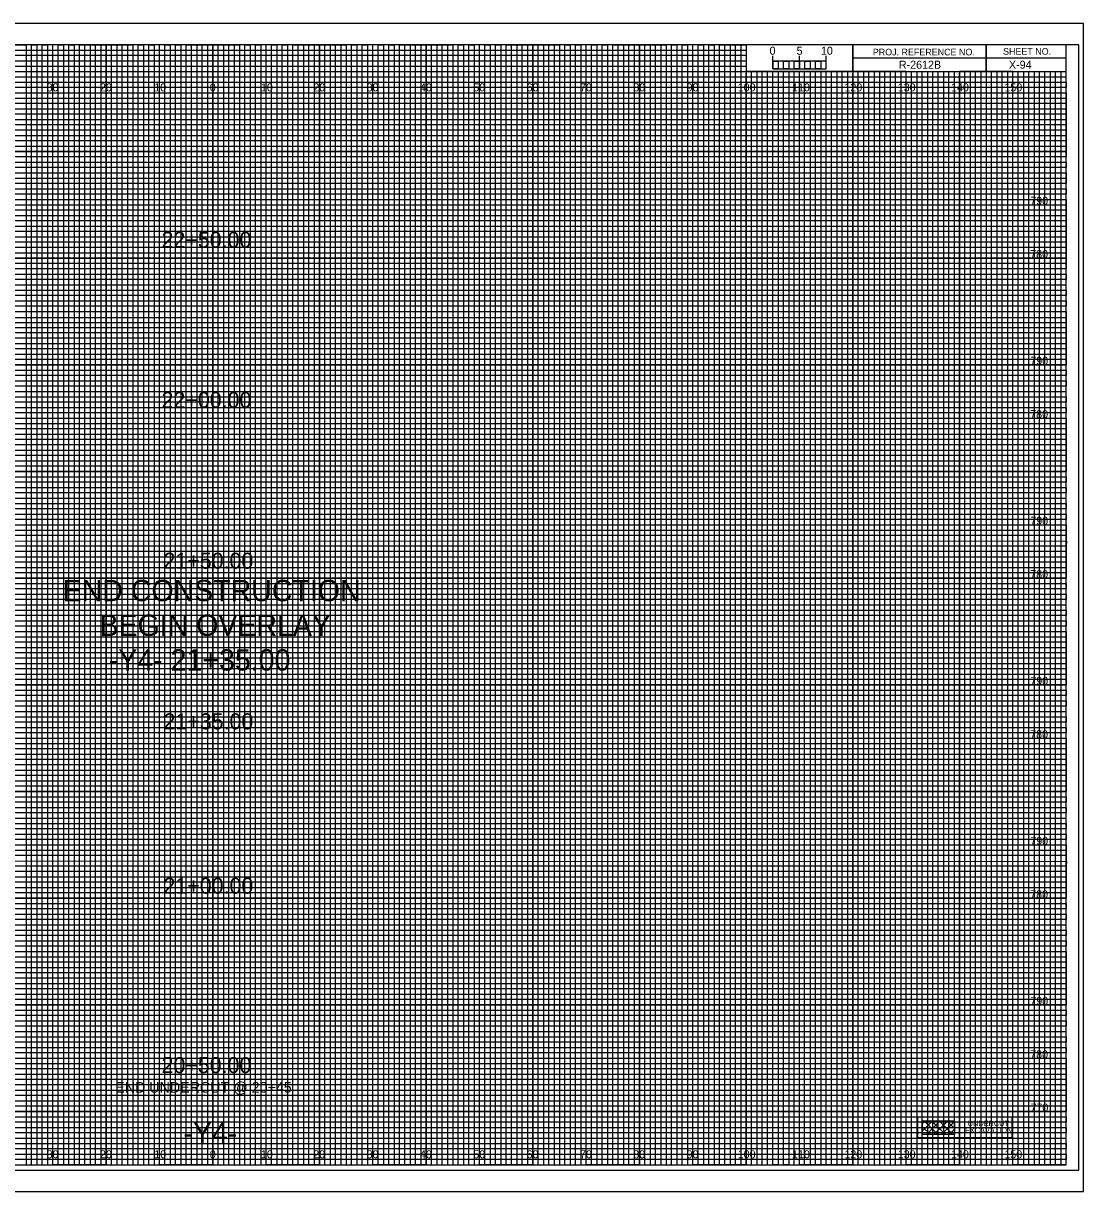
# Model space of a CAD drawing. Extents: x -13 to 323, y 875 to 1094.
# Drawn here: x 124.5 to 323.3, y 875 to 1094 of the extents above; entities that cross this region are included whole.
import ezdxf

# ---------------------------------------------------------------- set-up
doc = ezdxf.new("R2010")
doc.units = 0
for name, color, linetype in [('Prop Grid Mask', 7, 'Continuous'), ('Prop XS Alignment Label', 7, 'Continuous'), ('Prop XS Bar Scale Labels', 7, 'Continuous'), ('Prop XS Elevation Labels', 7, 'Continuous'), ('Prop XS Offset Labels', 7, 'Continuous'), ('Prop XS Project Number', 7, 'Continuous'), ('Prop XS Sheet Number', 7, 'Continuous'), ('Prop XS Station Labels', 7, 'Continuous'), ('Prop XS Undercut Exc Hatch', 7, 'Continuous'), ('Prop XSC Text', 7, 'Continuous'), ('Sheet Cross Section CELL', 7, 'Continuous'), ('Sheet Cross Section Grid Major CELL', 7, 'Continuous'), ('Sheet Cross Section Grid Middle CELL', 7, 'Continuous'), ('Sheet Cross Section Grid Minor 1 CELL', 7, 'Continuous'), ('Sheet Cross Section Grid Minor 2 CELL', 7, 'Continuous'), ('Sheet Cross Section Scale CELL', 7, 'Continuous'), ('Sheet Cutting Line CELL', 7, 'Continuous'), ('Sheet DOT Grid CELL', 7, 'Continuous'), ('Sheet Plot Border Inside CELL', 7, 'Continuous'), ('Sheet Plot Border Outside CELL', 7, 'Continuous')]:
    doc.layers.add(name, color=color, linetype=linetype)

msp = doc.modelspace()

# ---------------------------------------------------------------- linework, layer by layer
at = {"layer": 'Prop Grid Mask'}
for points in [[(292.21, 889.05), (309.86, 889.05), (309.86, 885.11), (292.21, 885.11)], [(293.02, 885.76), (299.12, 885.76), (299.12, 888.23), (293.02, 888.23)]]:
    msp.add_lwpolyline(points, close=True, dxfattribs=at)
at = {"layer": 'Prop XS Undercut Exc Hatch'}
for p, q in [((293.02, 887.74), (293.51, 888.23)), ((293.02, 886.33), (294.93, 888.23)), ((293.02, 887.24), (294.5, 885.76)), ((293.44, 888.23), (295.91, 885.76)), ((293.87, 885.76), (296.34, 888.23)), ((294.86, 888.23), (297.32, 885.76)), ((295.29, 885.76), (297.75, 888.23)), ((296.27, 888.23), (298.74, 885.76)), ((296.7, 885.76), (299.12, 888.18)), ((297.69, 888.23), (299.12, 886.79)), ((299.1, 888.23), (299.12, 888.21)), ((293.02, 885.82), (293.08, 885.76)), ((298.12, 885.76), (299.12, 886.77))]:
    msp.add_line(p, q, dxfattribs=at)
at = {"layer": 'Sheet Cross Section CELL'}
for p, q in [((305, 1090), (305, 1085)), ((305, 1085), (305, 1090)), ((280, 1087.5), (280, 1085)), ((320, 1087.49), (280, 1087.49)), ((280, 1085), (320, 1085))]:
    msp.add_line(p, q, dxfattribs=at)
for points in [[(320, 1090), (0, 1090), (0, 880), (320, 880)], [(280, 1090), (260, 1090), (260, 1085.03), (280, 1085.03)], [(320, 1090), (280, 1090), (280, 1085), (320, 1085)]]:
    msp.add_lwpolyline(points, close=True, dxfattribs=at)
at = {"layer": 'Sheet Cross Section Grid Major CELL'}
for p, q in [((130, 1090), (120, 1090)), ((130, 880), (130, 1090)), ((150, 1090), (140, 1090)), ((140, 1090), (140, 880)), ((150, 880), (150, 1090)), ((170, 1090), (160, 1090)), ((160, 1090), (160, 880)), ((170, 880), (170, 1090)), ((190, 1090), (180, 1090)), ((180, 1090), (180, 880)), ((190, 880), (190, 1090)), ((210, 1090), (200, 1090)), ((200, 1090), (200, 880)), ((210, 880), (210, 1090)), ((230, 1090), (220, 1090)), ((220, 1090), (220, 880)), ((230, 880), (230, 1090)), ((250, 1090), (240, 1090)), ((240, 1090), (240, 880)), ((250, 880), (250, 1090)), ((260, 1090), (260, 880)), ((270, 880), (270, 1085)), ((290, 1085), (280, 1085)), ((280, 1085), (280, 880)), ((290, 880), (290, 1085)), ((310, 1085), (300, 1085)), ((300, 1085), (300, 880)), ((310, 880), (310, 1085)), ((140, 880), (130, 880)), ((160, 880), (150, 880)), ((180, 880), (170, 880)), ((200, 880), (190, 880)), ((220, 880), (210, 880)), ((240, 880), (230, 880)), ((260, 880), (250, 880)), ((280, 880), (270, 880)), ((300, 880), (290, 880)), ((320, 880), (310, 880)), ((320, 880), (320, 880))]:
    msp.add_line(p, q, dxfattribs=at)
for points in [[(0, 1080), (320, 1080), (320, 1070), (0, 1070)], [(0, 1060), (320, 1060), (320, 1050), (0, 1050)], [(0, 1040), (320, 1040), (320, 1030), (0, 1030)], [(0, 1020), (320, 1020), (320, 1010), (0, 1010)], [(0, 1000), (320, 1000), (320, 990), (0, 990)], [(0, 980), (320, 980), (320, 970), (0, 970)], [(0, 960), (320, 960), (320, 950), (0, 950)], [(0, 940), (320, 940), (320, 930), (0, 930)], [(0, 920), (320, 920), (320, 910), (0, 910)], [(0, 900), (320, 900), (320, 890), (0, 890)]]:
    msp.add_lwpolyline(points, dxfattribs=at)
at = {"layer": 'Sheet Cross Section Grid Middle CELL'}
for points in [[(115, 1090), (125, 1090), (125, 880), (135, 880), (135, 1090), (145, 1090), (145, 880), (155, 880), (155, 1090), (165, 1090), (165, 880), (175, 880), (175, 1090), (185, 1090), (185, 880), (195, 880), (195, 1090), (205, 1090), (205, 880), (215, 880), (215, 1090), (225, 1090), (225, 880), (235, 880), (235, 1090), (245, 1090), (245, 880), (255, 880), (255, 1090), (259.93, 1090), (260, 1090), (260, 1085), (264.99, 1085), (264.99, 880), (275, 880), (275, 1085), (285, 1085), (285, 880), (295, 880), (295, 1085), (305, 1085), (305, 880), (315, 880), (315, 1085)], [(0, 1085), (275, 1085)], [(0, 1065), (320, 1065), (320, 1075), (0, 1075)], [(0, 1045), (320, 1045), (320, 1055), (0, 1055)], [(0, 1025), (320, 1025), (320, 1035), (0, 1035)], [(0, 1005), (320, 1005), (320, 1015), (0, 1015)], [(0, 985), (320, 985), (320, 995), (0, 995)], [(0, 965), (320, 965), (320, 975), (0, 975)], [(0, 945), (320, 945), (320, 955), (0, 955)], [(0, 925), (320, 925), (320, 935), (0, 935)], [(0, 905), (320, 905), (320, 915), (0, 915)], [(0, 885), (320, 885), (320, 895), (0, 895)]]:
    msp.add_lwpolyline(points, dxfattribs=at)
at = {"layer": 'Sheet Cross Section Grid Minor 1 CELL'}
for p, q in [((0, 1089), (260, 1089)), ((260, 1089), (260, 1087.98)), ((260, 1087.98), (0, 1087.98)), ((0, 1087), (260, 1087)), ((260, 1087), (260, 1085.89)), ((260, 1085.89), (0, 1085.89)), ((0, 1084), (320, 1084))]:
    msp.add_line(p, q, dxfattribs=at)
for points in [[(0, 1083), (270, 1083), (320, 1083), (320, 1082), (0, 1082)], [(0, 1081), (320, 1081), (320, 1079), (0, 1079)], [(0, 1078), (320, 1078), (320, 1077), (0, 1076.98)], [(0, 1076), (320, 1076), (320, 1074), (0, 1074)], [(0, 1073), (320, 1073), (320, 1072), (0, 1072)], [(0, 1071), (320, 1071), (320, 1069), (0, 1069)], [(0, 1068), (320, 1068), (320, 1067), (0, 1067)], [(0, 1066), (320, 1066), (320, 1064), (0, 1064)], [(0, 1063), (320, 1063), (320, 1062), (0, 1062)], [(0, 1061), (320, 1061), (320, 1059), (0, 1059)], [(0, 1058), (320, 1058), (320, 1057), (0, 1057)], [(0, 1056), (320, 1056), (320, 1053.95), (320, 1053), (320, 1052), (0, 1052)], [(0, 1054), (320, 1054), (320, 1053), (0, 1053)], [(0, 1051), (320, 1051), (320, 1049), (0, 1049.03)], [(0, 1049.03), (320, 1049), (320, 1048), (0, 1048)], [(0, 1047), (320, 1047), (320, 1046), (0, 1046)], [(0, 1044), (320, 1044), (320, 1043), (0, 1043)], [(0, 1042), (320, 1042), (320, 1041), (0, 1041)], [(-0.07, 1038.89), (320, 1038.89), (320, 1037.88), (-0.07, 1037.88)], [(0, 1037), (320, 1037), (320, 1036), (0, 1036)], [(0, 1034), (320, 1034), (320, 1033), (0, 1033)], [(0, 1032), (320, 1032), (320, 1031), (0, 1031)], [(0, 1029), (320, 1029), (320, 1028), (0, 1028)], [(0, 1027), (320, 1027), (320, 1026), (0, 1026)], [(0, 1024), (320, 1024), (320, 1023), (0, 1023)], [(0, 1022), (320, 1022), (320, 1021), (0, 1021)], [(0, 1019), (320, 1019), (319.99, 1017.98), (0, 1018)], [(0, 1017), (320, 1017), (320, 1016), (0, 1016)], [(0, 1014), (320, 1014), (320, 1013), (0, 1013)], [(0, 1012), (320, 1012), (320, 1011), (0, 1011)], [(0, 1009), (320, 1009), (320, 1008), (0, 1008)], [(0, 1007), (320, 1007), (320, 1006), (0, 1006)], [(0, 1004), (320, 1004), (320, 1003), (0, 1003)], [(0, 1002), (320, 1002), (320, 1001), (0, 1001)], [(0, 999), (320, 999), (320, 998), (0, 998)], [(0, 996.99), (320.07, 996.91), (320, 996), (0, 996)], [(0, 994), (320, 994), (320, 993), (0, 993)], [(0, 992), (320, 992), (320, 991), (0, 991)], [(0, 989), (320, 989), (320, 988), (0, 988)], [(0, 987), (320, 987), (320, 986), (0, 986)], [(0, 984), (320, 984), (320, 983), (0, 983)], [(0, 982), (320, 982), (320, 981), (0, 981)], [(0, 979), (320, 979), (320, 978), (0, 978)], [(0, 977), (320, 977), (320, 976), (0, 976)], [(0, 974), (320, 974), (320, 973), (0, 973)], [(0, 972), (320, 972), (320, 971), (0, 971)], [(0, 969), (320, 969), (320, 968), (0, 968)], [(0, 967), (320, 967), (320, 966), (0, 966)], [(0, 964), (320, 964), (320, 963), (0, 963)], [(0, 962), (320, 962), (320, 961), (0, 961)], [(0, 959), (320, 959), (319.99, 957.98), (0, 958)], [(0, 957), (320, 957), (320, 956), (0, 956)], [(0, 954), (320, 954), (320, 953), (0, 953)], [(0, 952), (320, 952), (320, 951), (0, 951)], [(0, 949), (320, 949), (320, 948), (0, 948)], [(0, 947), (320, 947), (320, 946), (0, 946)], [(0, 944), (320, 944), (320, 943), (0, 943)], [(0, 942), (320, 942), (320, 941), (0, 941)], [(0, 939), (320, 939), (320, 938), (0, 938)], [(0, 936.99), (320.07, 936.91), (320, 936), (0, 936)], [(0, 934), (320, 934), (320, 933), (0, 933)], [(0, 932), (320, 932), (320, 931), (0, 931)], [(0, 929), (320, 929), (320, 928), (0, 928)], [(0, 927), (320, 927), (320, 926), (0, 926)], [(0, 924), (320, 924), (320, 923), (0, 923)], [(0, 922), (320, 922), (320, 921), (0, 921)], [(0, 919), (320, 919), (320, 918), (0, 918)], [(0, 917), (320, 917), (320, 916), (0, 916)], [(0, 914), (320, 914), (320, 913), (0, 913)], [(0, 912), (320, 912), (320, 911), (0, 911)], [(0, 909), (320, 909), (320, 908), (0, 908)], [(0, 907), (320, 907), (320, 906), (0, 906)], [(0, 904), (320, 904), (320, 903), (0, 903)], [(0, 902), (320, 902), (320, 901), (0, 901)], [(0, 899), (320, 899), (320, 898), (0, 898)], [(0, 897), (320, 897), (320, 896), (0, 896)], [(0, 894), (320, 894), (320, 893), (0, 893)], [(0, 892), (320, 892), (320, 891), (0, 891)], [(0, 889), (320, 889), (320, 888), (0, 888)], [(0, 887), (320, 887), (320, 886), (0, 886)], [(0, 884), (320, 884), (320, 883), (0, 883)], [(0, 882), (320, 882), (320, 881), (0, 881)]]:
    msp.add_lwpolyline(points, dxfattribs=at)
at = {"layer": 'Sheet Cross Section Grid Minor 2 CELL'}
for p, q in [((267, 1085), (266.01, 1085)), ((266.01, 1085), (266.01, 880)), ((267, 880), (267, 1085)), ((269, 1085), (268, 1085)), ((268, 1085), (268, 880)), ((269, 880), (269, 1085)), ((266.01, 880), (265, 880)), ((268, 880), (267, 880))]:
    msp.add_line(p, q, dxfattribs=at)
for points in [[(125, 880), (126, 880), (126, 1090), (127, 1090), (127, 880)], [(127, 880), (128, 880), (128, 1090), (129, 1090), (129, 880)], [(130, 880), (131, 880), (131, 1090), (132, 1090), (132, 880)], [(132, 880), (133, 880), (133, 1090), (134, 1090), (134, 880)], [(135, 880), (136, 880), (136, 1090), (137, 1090), (137, 880)], [(137, 880), (138, 880), (138, 1090), (139, 1090), (139, 880)], [(140, 880), (141, 880), (141, 1090), (142, 1090), (142, 880)], [(142, 880), (143, 880), (143, 1090), (144, 1090), (144, 880)], [(145, 880), (146, 880), (146, 1090), (147, 1090), (147, 880)], [(147, 880), (148, 880), (148, 1090), (149, 1090), (149, 880)], [(150, 880), (151, 880), (151, 1090), (152, 1090), (152, 880)], [(152, 880), (153, 880), (153, 1090), (154, 1090), (154, 880)], [(155, 880), (156, 880), (156, 1090), (157, 1090), (157, 880)], [(157, 880), (158, 880), (158, 1090), (159, 1090), (159, 880)], [(160, 880), (161, 880), (161, 1090), (162, 1090), (162, 880)], [(162, 880), (163, 880), (163, 1090), (164, 1090), (164, 880)], [(165, 880), (166, 880), (166, 1090), (167, 1090), (167, 880)], [(167, 880), (168, 880), (168, 1090), (169, 1090), (169, 880)], [(170, 880), (171, 880), (171, 1090), (172, 1090), (172, 880)], [(172, 880), (173, 880), (173, 1090), (174, 1090), (174, 880)], [(175, 880), (176, 880), (176, 1090), (177, 1090), (177, 880)], [(177, 880), (178, 880), (178, 1090), (179, 1090), (179, 880)], [(180, 880), (181, 880), (181, 1090), (182, 1090), (182, 880)], [(182, 880), (183, 880), (183, 1090), (184, 1090), (184, 880)], [(185, 880), (186, 880), (186, 1090), (187, 1090), (187, 880)], [(187, 880), (188, 880), (188, 1090), (189, 1090), (189, 880)], [(190, 880), (191, 880), (191, 1090), (192, 1090), (192, 880)], [(192, 880), (193, 880), (193, 1090), (194, 1090), (194, 880)], [(195, 880), (196, 880), (196, 1090), (197, 1090), (197, 880)], [(197, 880), (198, 880), (198, 1090), (199, 1090), (199, 880)], [(200, 880), (201, 880), (201, 1090), (202, 1090), (202, 880)], [(202, 880), (203, 880), (203, 1090), (204, 1090), (204, 880)], [(205, 880), (206, 880), (206, 1090), (207, 1090), (207, 880)], [(207, 880), (208, 880), (208, 1090), (209, 1090), (209, 880)], [(210, 880), (211, 880), (211, 1090), (212, 1090), (212, 880)], [(212, 880), (213, 880), (213, 1090), (214, 1090), (214, 880)], [(215, 880), (216, 880), (216, 1090), (217, 1090), (217, 880)], [(217, 880), (218, 880), (218, 1090), (219, 1090), (219, 880)], [(220, 880), (221, 880), (221, 1090), (222, 1090), (222, 880)], [(222, 880), (223, 880), (223, 1090), (224, 1090), (224, 880)], [(225, 880), (226, 880), (226, 1090), (227, 1090), (227, 880)], [(227, 880), (228, 880), (228, 1090), (229, 1090), (229, 880)], [(230, 880), (231, 880), (231, 1090), (232, 1090), (232, 880)], [(232, 880), (233, 880), (233, 1090), (234, 1090), (234, 880)], [(235, 880), (236, 880), (236, 1090), (237, 1090), (237, 880)], [(237, 880), (238, 880), (238, 1090), (239, 1090), (239, 880)], [(240, 880), (241, 880), (241, 1090), (242, 1090), (242, 880)], [(242, 880), (243, 880), (243, 1090), (244, 1090), (244, 880)], [(245, 880), (246, 880), (246, 1090), (247, 1090), (247, 880)], [(247, 880), (248, 880), (248, 1090), (249, 1090), (249, 880)], [(250, 880), (251, 880), (251, 1090), (252, 1090), (252, 880)], [(252, 880), (253, 880), (253, 1090), (254, 1090), (254, 880)], [(255, 880), (256, 880), (256, 1090), (257, 1090), (257, 880)], [(257, 880), (258, 880), (258, 1090), (259, 1090), (259, 880)], [(260, 880), (261, 880), (261, 1085), (262.02, 1085), (262.02, 880)], [(262, 880), (263, 880), (263, 1085), (263.99, 1085), (263.99, 880)], [(270, 880), (270.98, 880), (270.98, 1085), (272, 1085), (272, 880)], [(272, 880), (273, 880), (273, 1085), (274.05, 1085), (274.05, 880)], [(275, 880), (276, 880), (276, 1085), (277, 1085), (277, 880)], [(277, 880), (278, 880), (278, 1085), (279, 1085), (279, 880)], [(280, 880), (281, 880), (281, 1085), (282, 1085), (282, 880)], [(282, 880), (283, 880), (283, 1085), (284, 1085), (284, 880)], [(285, 880), (286, 880), (286, 1085), (287, 1085), (287, 880)], [(287, 880), (288, 880), (288, 1085), (289, 1085), (289, 880)], [(290, 880), (291, 880), (291, 1085), (292, 1085), (292, 880)], [(292, 880), (293, 880), (293, 1085), (294, 1085), (294, 880)], [(295, 880), (296, 880), (296, 1085), (297, 1085), (297, 880)], [(297, 880), (298, 880), (298, 1085), (299, 1085), (299, 880)], [(300, 880), (301, 880), (301, 1085), (302, 1085), (302, 880)], [(302, 880), (303, 880), (303, 1085), (304, 1085), (304, 880)], [(305, 880), (306, 880), (306, 1085), (307, 1085), (307, 880)], [(307, 880), (308, 880), (308, 1085), (309, 1085), (309, 880)], [(310, 880), (311, 880), (311, 1085), (312, 1085), (312, 880)], [(312, 880), (313, 880), (313, 1085), (314, 1085), (314, 880)], [(315, 880), (316, 880), (316, 1085), (317, 1085), (317, 880)], [(317, 880), (318, 880), (318, 1085), (319, 1085), (319, 880)]]:
    msp.add_lwpolyline(points, dxfattribs=at)
at = {"layer": 'Sheet Cross Section Scale CELL'}
for p, q in [((265, 1085.49), (265, 1087.9)), ((265, 1086.9), (265, 1087.9)), ((270, 1085.49), (270, 1087.9)), ((275, 1085.49), (275, 1087.9)), ((275, 1086.9), (275, 1087.9))]:
    msp.add_line(p, q, dxfattribs=at)
for points in [[(275, 1086.9), (265, 1086.9), (265, 1085.49), (275, 1085.49)], [(265, 1086.9), (266, 1086.9), (266, 1085.49), (265, 1085.49)], [(267, 1086.9), (268, 1086.9), (268, 1085.49), (267, 1085.49)], [(269, 1086.9), (270, 1086.9), (270, 1085.49), (269, 1085.49)], [(271, 1086.9), (272, 1086.9), (272, 1085.49), (271, 1085.49)], [(273, 1086.9), (274, 1086.9), (274, 1085.49), (273, 1085.49)]]:
    msp.add_lwpolyline(points, close=True, dxfattribs=at)
at = {"layer": 'Sheet Cutting Line CELL'}
for p, q in [((323.3, 1094), (-13.4, 1094)), ((-13.4, 875), (323.3, 875))]:
    msp.add_line(p, q, dxfattribs=at)
at = {"layer": 'Sheet DOT Grid CELL'}
for p, q in [((130, 880), (130, 1090)), ((140, 880), (140, 1090)), ((150, 880), (150, 1090)), ((160, 880), (160, 1090)), ((170, 880), (170, 1090)), ((180, 880), (180, 1090)), ((190, 880), (190, 1090)), ((200, 880), (200, 1090)), ((210, 880), (210, 1090)), ((220, 880), (220, 1090)), ((230, 880), (230, 1090)), ((240, 880), (240, 1090)), ((250, 880), (250, 1090)), ((260, 880), (260, 1084.69)), ((270, 880), (270, 1084.69)), ((280, 880), (280, 1084.69)), ((290, 880), (290, 1084.69)), ((300, 880), (300, 1084.69)), ((310, 880), (310, 1084.69)), ((0, 1080), (320, 1080)), ((0, 1070), (320, 1070)), ((0, 1060), (320, 1060)), ((0, 1050), (320, 1050)), ((0, 1040), (320, 1040)), ((0, 1030), (320, 1030)), ((0, 1020), (320, 1020)), ((0, 1010), (320, 1010)), ((0, 1000), (320, 1000)), ((0, 990), (320, 990)), ((0, 980), (320, 980)), ((0, 970), (320, 970)), ((0, 960), (320, 960)), ((0, 950), (320, 950)), ((0, 940), (320, 940)), ((0, 930), (320, 930)), ((0, 920), (320, 920)), ((0, 910), (320, 910)), ((0, 900), (320, 900)), ((0, 890), (320, 890))]:
    msp.add_line(p, q, dxfattribs=at)
at = {"layer": 'Sheet Plot Border Inside CELL'}
msp.add_lwpolyline([(-10.8, 879), (322.4, 879), (322.4, 1090), (-10.8, 1090)], close=True, dxfattribs=at)
at = {"layer": 'Sheet Plot Border Outside CELL'}
msp.add_lwpolyline([(-13.4, 875), (323.3, 875), (323.3, 1094), (-13.4, 1094)], close=True, dxfattribs=at)

# ---------------------------------------------------------------- texts
at = {"layer": 'Prop Grid Mask'}
msp.add_text('END UNDERCUT @ 20+45', height=2, dxfattribs=at).set_placement((141.72, 893.55))
at = {"layer": 'Prop XS Alignment Label'}
for s, p in [('END CONSTRUCTION', (131.87, 985.68)), ('BEGIN OVERLAY', (138.78, 979.18)), ('-Y4- 21+35.00', (140.52, 972.68)), ('-Y4-', (154.52, 884))]:
    msp.add_text(s, height=4, dxfattribs=at).set_placement(p)
at = {"layer": 'Prop XS Bar Scale Labels'}
for s, p in [('5', (269.47, 1088.12)), ('10', (274.04, 1088.12))]:
    msp.add_text(s, height=1.5, dxfattribs=at).set_placement(p)
at = {"layer": 'Prop XS Elevation Labels'}
for s, p in [('790', (313.3, 1060)), ('780', (313.28, 1050)), ('790', (313.3, 1030)), ('780', (313.28, 1020)), ('790', (313.3, 1000)), ('780', (313.28, 990)), ('790', (313.3, 970)), ('780', (313.28, 960)), ('790', (313.3, 940)), ('780', (313.28, 930)), ('790', (313.3, 910)), ('780', (313.28, 900)), ('770', (313.33, 890))]:
    msp.add_text(s, height=1.5, dxfattribs=at).set_placement(p)
at = {"layer": 'Prop XS Offset Labels'}
for s, p in [('30', (128.86, 1081.25)), ('20', (138.86, 1081.25)), ('10', (149.04, 1081.25)), ('0', (159.45, 1081.25)), ('0', (159.45, 1081.25)), ('10', (169.04, 1081.25)), ('20', (178.86, 1081.25)), ('30', (188.86, 1081.25)), ('40', (198.86, 1081.25)), ('50', (208.86, 1081.25)), ('60', (218.86, 1081.25)), ('70', (228.86, 1081.25)), ('80', (238.86, 1081.25)), ('90', (248.86, 1081.25)), ('100', (258.44, 1081.25)), ('110', (268.62, 1081.25)), ('120', (278.44, 1081.25)), ('130', (288.44, 1081.25)), ('140', (298.44, 1081.25)), ('150', (308.44, 1081.25)), ('30', (128.86, 881.25)), ('20', (138.86, 881.25)), ('10', (149.04, 881.25)), ('0', (159.45, 881.25)), ('0', (159.45, 881.25)), ('10', (169.04, 881.25)), ('20', (178.86, 881.25)), ('30', (188.86, 881.25)), ('40', (198.86, 881.25)), ('50', (208.86, 881.25)), ('60', (218.86, 881.25)), ('70', (228.86, 881.25)), ('80', (238.86, 881.25)), ('90', (248.86, 881.25)), ('100', (258.44, 881.25)), ('110', (268.62, 881.25)), ('120', (278.44, 881.25)), ('130', (288.44, 881.25)), ('140', (298.44, 881.25)), ('150', (308.44, 881.25))]:
    msp.add_text(s, height=1.5, dxfattribs=at).set_placement(p)
at = {"layer": 'Prop XS Project Number'}
msp.add_text('R-2612B', height=1.5, dxfattribs=at).set_placement((288.66, 1085.5))
at = {"layer": 'Prop XS Sheet Number'}
msp.add_text('X-94', height=1.5, dxfattribs=at).set_placement((309.3, 1085.5))
at = {"layer": 'Prop XS Station Labels'}
for s, p in [('22+50.00', (150.41, 1051.93)), ('22+00.00', (150.41, 1021.91)), ('21+50.00', (150.77, 991.77)), ('21+35.00', (150.77, 961.66)), ('21+00.00', (150.77, 930.85)), ('20+50.00', (150.41, 897.22))]:
    msp.add_text(s, height=3, dxfattribs=at).set_placement(p)
at = {"layer": 'Prop XSC Text'}
for s, p in [('EXCAVATION', (301.04, 886)), ('UNDERCUT', (301.56, 887.31))]:
    msp.add_text(s, height=1, dxfattribs=at).set_placement(p)
at = {"layer": 'Sheet Cross Section CELL'}
for s, p in [('PROJ. REFERENCE NO.', (283.77, 1087.99)), ('SHEET NO.', (308.19, 1088.12))]:
    msp.add_text(s, height=1.25, dxfattribs=at).set_placement(p)
at = {"layer": 'Sheet Cross Section Scale CELL'}
msp.add_text('0', height=1.5, dxfattribs=at).set_placement((264.41, 1088.12))

doc.saveas('drawing.dxf')
